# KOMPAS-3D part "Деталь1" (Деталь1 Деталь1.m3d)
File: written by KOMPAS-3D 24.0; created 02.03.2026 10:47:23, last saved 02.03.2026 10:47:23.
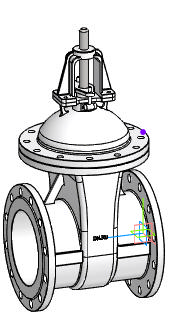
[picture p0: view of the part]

Document properties: Автор: R2D2; Полное имя файла: E:\Работа\Зайцев\GVWR3131M-2W-F-S Задвижка клиновая с выдвижным штоком DN.ru Ду50-200 Ру63\DN200\исходные материалы\Деталь1 Деталь1.m3d

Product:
- Body: Твердое тело1  | qty 1  | 5 such rows
- Part/product: Деталь1
    additional columns: Типовые

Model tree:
1. Твердое тело1  (labels: Твердое тело1)
2. Точка:1
     Y = 280.5; Координата Y = 280.5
